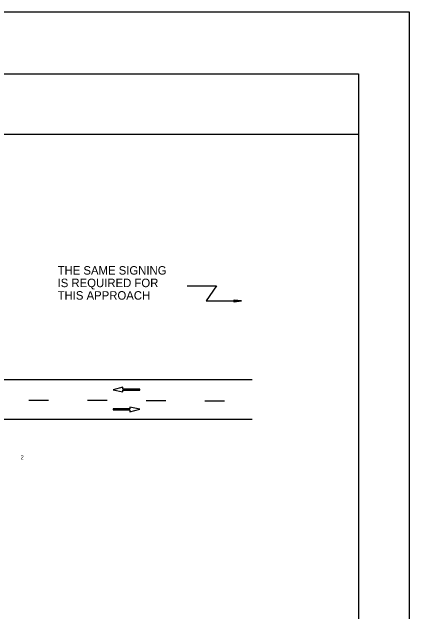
# Model space of a CAD drawing. Extents: x -14145 to -13662, y 30244 to 30661.
# Drawn here: x -13767.01 to -13757.17, y 30516.47 to 30531.31 of the extents above; entities that cross this region are included whole.
import ezdxf

# ---------------------------------------------------------------- set-up
doc = ezdxf.new("R2010")
doc.units = 0
for name, color, linetype in [('1', 7, 'Continuous'), ('10', 7, 'Continuous'), ('2', 7, 'Continuous'), ('3', 7, 'Continuous'), ('61', 7, 'Continuous')]:
    doc.layers.add(name, color=color, linetype=linetype)

msp = doc.modelspace()

# ---------------------------------------------------------------- linework, layer by layer
at = {"layer": '1'}
for p, q in [((-13762.668, 30524.525), (-13761.942, 30524.525)), ((-13761.942, 30524.526), (-13762.194, 30524.153)), ((-13762.194, 30524.153), (-13761.323, 30524.153)), ((-13787.336, 30522.204), (-13761.056, 30522.204)), ((-13764.262, 30522.012), (-13764.503, 30521.946)), ((-13764.262, 30521.967), (-13764.262, 30522.012)), ((-13764.503, 30521.946), (-13764.259, 30521.9)), ((-13763.845, 30521.967), (-13764.262, 30521.967)), ((-13764.259, 30521.9), (-13764.259, 30521.945)), ((-13764.259, 30521.945), (-13763.845, 30521.945)), ((-13763.845, 30521.945), (-13763.845, 30521.967)), ((-13766.104, 30521.688), (-13766.59, 30521.688)), ((-13764.652, 30521.682), (-13765.138, 30521.682)), ((-13763.2, 30521.676), (-13763.686, 30521.676)), ((-13761.748, 30521.67), (-13762.234, 30521.67)), ((-13764.089, 30521.476), (-13764.503, 30521.476)), ((-13764.503, 30521.476), (-13764.503, 30521.454)), ((-13764.503, 30521.454), (-13764.087, 30521.454)), ((-13763.845, 30521.475), (-13764.089, 30521.521)), ((-13764.089, 30521.521), (-13764.089, 30521.476)), ((-13764.087, 30521.409), (-13763.845, 30521.475)), ((-13764.087, 30521.454), (-13764.087, 30521.409)), ((-13787.336, 30521.22), (-13761.056, 30521.22))]:
    msp.add_line(p, q, dxfattribs=at)
msp.add_lwpolyline([(-13761.502, 30524.174), (-13761.494, 30524.16), (-13761.322, 30524.152), (-13761.502, 30524.174), (-13761.507, 30524.181), (-13761.322, 30524.152), (-13761.493, 30524.14), (-13761.501, 30524.13), (-13761.322, 30524.152), (-13761.51, 30524.12), (-13761.501, 30524.13)], dxfattribs=at)
at = {"layer": '10'}
for p, q in [((-13789.874, 30529.777), (-13758.422, 30529.777)), ((-13758.422, 30529.777), (-13758.422, 30507.207)), ((-13789.874, 30528.277), (-13758.422, 30528.277))]:
    msp.add_line(p, q, dxfattribs=at)
at = {"layer": '61'}
msp.add_lwpolyline([(-13790.174, 30531.307), (-13757.174, 30531.307), (-13757.174, 30505.807), (-13790.174, 30505.807)], close=True, dxfattribs=at)

# ---------------------------------------------------------------- texts
at = {"layer": '2'}
for s, p in [('THE SAME SIGNING', (-13765.878, 30524.803)), ('IS REQUIRED FOR', (-13765.878, 30524.493)), ('THIS APPROACH', (-13765.878, 30524.183))]:
    msp.add_text(s, height=0.21, dxfattribs=at).set_placement(p)
at = {"layer": '3'}
msp.add_text('2', height=0.1, dxfattribs=at).set_placement((-13766.794, 30520.23))

doc.saveas('drawing.dxf')
